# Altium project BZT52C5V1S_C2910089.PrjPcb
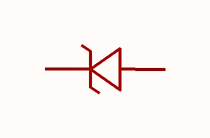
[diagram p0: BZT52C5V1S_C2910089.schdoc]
1 sheet, 1 parts. Net scope: global (net labels, ports and power ports of the same name join across sheets).

## Sheet BZT52C5V1S_C2910089.schdoc
size 127 x 101 mm

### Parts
D?  bzt52c5v1s_c2910089  [SOD-323_L1.7-W1.3-LS2.6-RD]  (value not drawn)

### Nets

Not connected (* = marked no-connect by the designer): D? 1(K) 2(A)

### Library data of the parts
D? = bzt52c5v1s_c2910089: 二极管配置:1个独立式;稳压值(标称值):5.1V;稳压值(范围):4.8V~5.4V;耗散功率(Pd):200mW;; Manufacturer: CJ(江苏长电/长晶); AddInBom: yes; ModelId: 8f7582057468434a979d3a4d6e318d8a; ModelTransform: 100.394,49.2125,0,0,0,0,0,0,0; Diode Configuration: 1个独立式; Zener Voltage(Nom): 5.1V; Reverse Leakage Current (Ir): 2uA@2V; Pd - Power Dissipation: 200mW; Impedance(Zzt): 60Ω; Impedance(Zzk): 480Ω; Operating Junction Temperature Range: -55℃~+150℃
